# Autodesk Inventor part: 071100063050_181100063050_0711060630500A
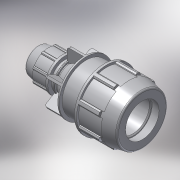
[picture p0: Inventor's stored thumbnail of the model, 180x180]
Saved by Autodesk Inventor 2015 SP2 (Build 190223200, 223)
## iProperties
Created: 2017-02
Part Number: 071100063050_181100063050_0711060630500A
Material: PVC-Piping
Description: PLASSON REDUCING COUPLER 63-50
Document SubType Name: Modeling
Designer: KIM
Mass: 92.6774 g
Surface Area: 199.44 cm^2
Volume: 66.1981 cm^3
Density: 1.4 g/cm^3
Appearance: Smooth - White
Author: KIM
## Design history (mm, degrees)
derived "07110.ipt"
feature "Solid1::07110.ipt"
tag "TaggingFeature1"
body "Solid1"
other parameters: "d2" = 63, "d4" = 17.83333, "d5" = 30.57143, "d7" = 113, "d9" = 30.57143, "d11" = 3.05714, "d12" = 90.4, "d13" = 120 deg, "d14" = 94.5, "d15" = 12 deg, "d16" = 101.7, "d18" = 3.15, "d19" = 35 deg, "d20" = 17.5 deg, "d21" = 105.09, "d23" = 0, "d25" = 360 deg, "d27" = 2.26, "d42" = 47.08, "d46" = 1.89, "d51" = 214, "d52" = 30.57143, "d53" = 12 deg, "d56" = 75, "d58" = 56.7, "d59" = 45, "d60" = 86.4, "d61" = 76.8, "d62" = 21.4, "d63" = 34.24, "d64" = 120 deg, "d65" = 96, "d68" = 15.28571, "d74" = 89.28, "d75" = 35 deg, "d76" = 17.5 deg, "d78" = 0, "d80" = 360 deg, "d85" = 1.92, "d88" = 1, "d93" = 93, "d94" = 79.1, "d97" = 2.9, "d98" = 6.4, "d99" = 0, "d100" = 4.52, "d102" = 360 deg, "d104" = 2, "d106" = 0, "d107" = 6.4, "d108" = 0, "d109" = 6.4, "d110" = 0, "d_" = 63, "E_" = 113, "H_" = 214, "E_1" = 96, "l_1" = 93, "d96" = 8.7
